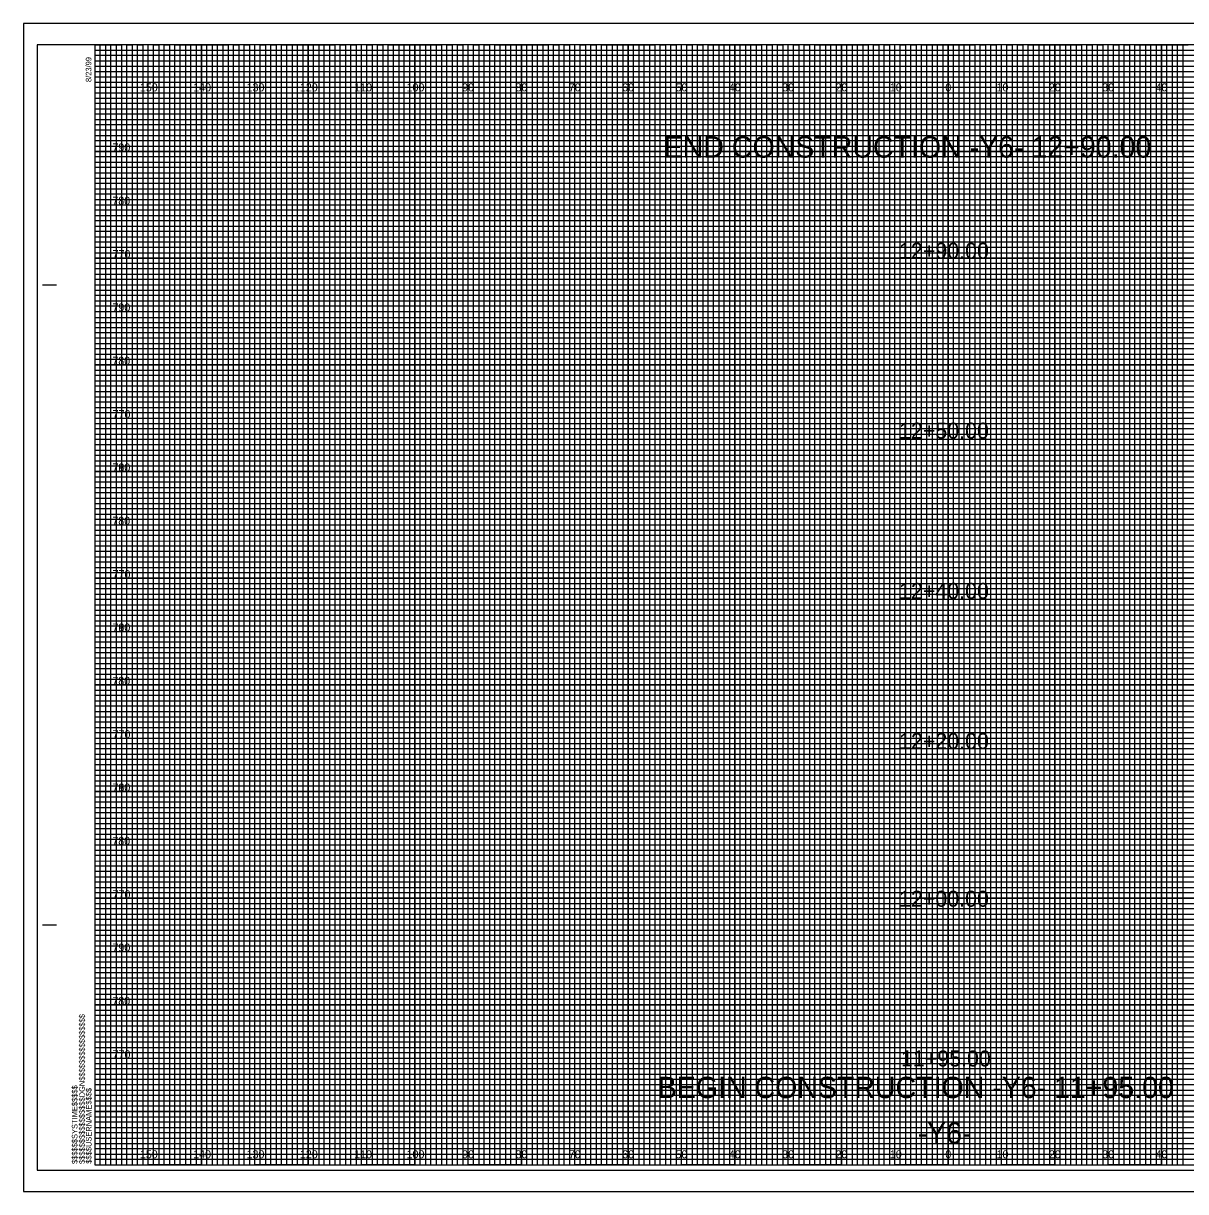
# Model space of a CAD drawing. Extents: x -13 to 323, y -5 to 214.
# Drawn here: x -13.4 to 204.5, y -5 to 214 of the extents above; entities that cross this region are included whole.
import ezdxf

# ---------------------------------------------------------------- set-up
doc = ezdxf.new("R2010")
doc.units = 0
for name, color, linetype in [('Prop XS Alignment Label', 7, 'Continuous'), ('Prop XS Elevation Labels', 7, 'Continuous'), ('Prop XS Offset Labels', 7, 'Continuous'), ('Prop XS Station Labels', 7, 'Continuous'), ('Sheet Cross Section CELL', 7, 'Continuous'), ('Sheet Cross Section Grid Major CELL', 7, 'Continuous'), ('Sheet Cross Section Grid Middle CELL', 7, 'Continuous'), ('Sheet Cross Section Grid Minor 1 CELL', 7, 'Continuous'), ('Sheet Cross Section Grid Minor 2 CELL', 7, 'Continuous'), ('Sheet Cutting Line CELL', 7, 'Continuous'), ('Sheet DOT Grid CELL', 7, 'Continuous'), ('Sheet Plot Border Inside CELL', 7, 'Continuous'), ('Sheet Plot Border Outside CELL', 7, 'Continuous')]:
    doc.layers.add(name, color=color, linetype=linetype)

msp = doc.modelspace()

# ---------------------------------------------------------------- linework, layer by layer
at = {"layer": 'Sheet Cross Section CELL'}
for p, q in [((-9.8, 165), (-7.3, 165)), ((-9.7, 165), (-7.2, 165)), ((-9.8, 45), (-7.3, 45)), ((-9.7, 45), (-7.2, 45)), ((0, 0), (0, 0)), ((0, 0), (0, 0)), ((0, 0), (0, 0)), ((0, 0), (0, 0)), ((0, 0), (0, 0)), ((0, 0), (0, 0)), ((0, 0), (0, 0))]:
    msp.add_line(p, q, dxfattribs=at)
msp.add_lwpolyline([(320, 210), (0, 210), (0, 0), (320, 0)], close=True, dxfattribs=at)
at = {"layer": 'Sheet Cross Section Grid Major CELL'}
for p, q in [((10, 210), (0, 210)), ((10, 0), (10, 210)), ((30, 210), (20, 210)), ((20, 210), (20, 0)), ((30, 0), (30, 210)), ((50, 210), (40, 210)), ((40, 210), (40, 0)), ((50, 0), (50, 210)), ((70, 210), (60, 210)), ((60, 210), (60, 0)), ((70, 0), (70, 210)), ((90, 210), (80, 210)), ((80, 210), (80, 0)), ((90, 0), (90, 210)), ((110, 210), (100, 210)), ((100, 210), (100, 0)), ((110, 0), (110, 210)), ((130, 210), (120, 210)), ((120, 210), (120, 0)), ((130, 0), (130, 210)), ((150, 210), (140, 210)), ((140, 210), (140, 0)), ((150, 0), (150, 210)), ((170, 210), (160, 210)), ((160, 210), (160, 0)), ((170, 0), (170, 210)), ((190, 210), (180, 210)), ((180, 210), (180, 0)), ((190, 0), (190, 210)), ((210, 210), (200, 210)), ((200, 210), (200, 0)), ((20, 0), (10, 0)), ((40, 0), (30, 0)), ((60, 0), (50, 0)), ((80, 0), (70, 0)), ((100, 0), (90, 0)), ((120, 0), (110, 0)), ((140, 0), (130, 0)), ((160, 0), (150, 0)), ((180, 0), (170, 0)), ((200, 0), (190, 0))]:
    msp.add_line(p, q, dxfattribs=at)
for points in [[(0, 200), (320, 200), (320, 190), (0, 190)], [(0, 180), (320, 180), (320, 170), (0, 170)], [(0, 160), (320, 160), (320, 150), (0, 150)], [(0, 140), (320, 140), (320, 130), (0, 130)], [(0, 120), (320, 120), (320, 110), (0, 110)], [(0, 100), (320, 100), (320, 90), (0, 90)], [(0, 80), (320, 80), (320, 70), (0, 70)], [(0, 60), (320, 60), (320, 50), (0, 50)], [(0, 40), (320, 40), (320, 30), (0, 30)], [(0, 20), (320, 20), (320, 10), (0, 10)]]:
    msp.add_lwpolyline(points, dxfattribs=at)
at = {"layer": 'Sheet Cross Section Grid Middle CELL'}
for points in [[(0, 210), (5, 210), (5, 0), (15, 0), (15, 210), (25, 210), (25, 0), (35, 0), (35, 210), (45, 210), (45, 0), (55, 0), (55, 210), (65, 210), (65, 0), (75, 0), (75, 210), (85, 210), (85, 0), (95, 0), (95, 210), (105, 210), (105, 0), (115, 0), (115, 210), (125, 210), (125, 0), (135, 0), (135, 210), (145, 210), (145, 0), (155, 0), (155, 210), (165, 210), (165, 0), (175, 0), (175, 210), (185, 210), (185, 0), (195, 0), (195, 210), (205, 210)], [(0, 205), (275, 205)], [(0, 185), (320, 185), (320, 195), (0, 195)], [(0, 165), (320, 165), (320, 175), (0, 175)], [(0, 145), (320, 145), (320, 155), (0, 155)], [(0, 125), (320, 125), (320, 135), (0, 135)], [(0, 105), (320, 105), (320, 115), (0, 115)], [(0, 85), (320, 85), (320, 95), (0, 95)], [(0, 65), (320, 65), (320, 75), (0, 75)], [(0, 45), (320, 45), (320, 55), (0, 55)], [(0, 25), (320, 25), (320, 35), (0, 35)], [(0, 5), (320, 5), (320, 15), (0, 15)]]:
    msp.add_lwpolyline(points, dxfattribs=at)
at = {"layer": 'Sheet Cross Section Grid Minor 1 CELL'}
for p, q in [((0, 209), (260, 209)), ((260, 207.98), (0, 207.98)), ((0, 207.98), (0, 207)), ((0, 207), (260, 207)), ((260, 205.89), (0, 205.89)), ((0, 205.89), (0, 204)), ((0, 204), (320, 204))]:
    msp.add_line(p, q, dxfattribs=at)
for points in [[(0, 203), (270, 203), (320, 203), (320, 202), (0, 202)], [(0, 201), (320, 201), (320, 199), (0, 199)], [(0, 198), (320, 198), (320, 197), (0, 196.98)], [(0, 196), (320, 196), (320, 194), (0, 194)], [(0, 193), (320, 193), (320, 192), (0, 192)], [(0, 191), (320, 191), (320, 189), (0, 189)], [(0, 188), (320, 188), (320, 187), (0, 187)], [(0, 186), (320, 186), (320, 184), (0, 184)], [(0, 183), (320, 183), (320, 182), (0, 182)], [(0, 181), (320, 181), (320, 179), (0, 179)], [(0, 178), (320, 178), (320, 177), (0, 177)], [(0, 176), (320, 176), (320, 173.95), (320, 173), (320, 172), (0, 172)], [(0, 174), (320, 174), (320, 173), (0, 173)], [(0, 171), (320, 171), (320, 169), (0, 169.03)], [(0, 169.03), (320, 169), (320, 168), (0, 168)], [(0, 167), (320, 167), (320, 166), (0, 166)], [(0, 164), (320, 164), (320, 163), (0, 163)], [(0, 162), (320, 162), (320, 161), (0, 161)], [(-0.07, 158.89), (320, 158.89), (320, 157.88), (-0.07, 157.88)], [(0, 157), (320, 157), (320, 156), (0, 156)], [(0, 154), (320, 154), (320, 153), (0, 153)], [(0, 152), (320, 152), (320, 151), (0, 151)], [(0, 149), (320, 149), (320, 148), (0, 148)], [(0, 147), (320, 147), (320, 146), (0, 146)], [(0, 144), (320, 144), (320, 143), (0, 143)], [(0, 142), (320, 142), (320, 141), (0, 141)], [(0, 139), (320, 139), (319.99, 137.98), (0, 138)], [(0, 137), (320, 137), (320, 136), (0, 136)], [(0, 134), (320, 134), (320, 133), (0, 133)], [(0, 132), (320, 132), (320, 131), (0, 131)], [(0, 129), (320, 129), (320, 128), (0, 128)], [(0, 127), (320, 127), (320, 126), (0, 126)], [(0, 124), (320, 124), (320, 123), (0, 123)], [(0, 122), (320, 122), (320, 121), (0, 121)], [(0, 119), (320, 119), (320, 118), (0, 118)], [(0, 116.99), (320.07, 116.91), (320, 116), (0, 116)], [(0, 114), (320, 114), (320, 113), (0, 113)], [(0, 112), (320, 112), (320, 111), (0, 111)], [(0, 109), (320, 109), (320, 108), (0, 108)], [(0, 107), (320, 107), (320, 106), (0, 106)], [(0, 104), (320, 104), (320, 103), (0, 103)], [(0, 102), (320, 102), (320, 101), (0, 101)], [(0, 99), (320, 99), (320, 98), (0, 98)], [(0, 97), (320, 97), (320, 96), (0, 96)], [(0, 94), (320, 94), (320, 93), (0, 93)], [(0, 92), (320, 92), (320, 91), (0, 91)], [(0, 89), (320, 89), (320, 88), (0, 88)], [(0, 87), (320, 87), (320, 86), (0, 86)], [(0, 84), (320, 84), (320, 83), (0, 83)], [(0, 82), (320, 82), (320, 81), (0, 81)], [(0, 79), (320, 79), (319.99, 77.98), (0, 78)], [(0, 77), (320, 77), (320, 76), (0, 76)], [(0, 74), (320, 74), (320, 73), (0, 73)], [(0, 72), (320, 72), (320, 71), (0, 71)], [(0, 69), (320, 69), (320, 68), (0, 68)], [(0, 67), (320, 67), (320, 66), (0, 66)], [(0, 64), (320, 64), (320, 63), (0, 63)], [(0, 62), (320, 62), (320, 61), (0, 61)], [(0, 59), (320, 59), (320, 58), (0, 58)], [(0, 56.99), (320.07, 56.91), (320, 56), (0, 56)], [(0, 54), (320, 54), (320, 53), (0, 53)], [(0, 52), (320, 52), (320, 51), (0, 51)], [(0, 49), (320, 49), (320, 48), (0, 48)], [(0, 47), (320, 47), (320, 46), (0, 46)], [(0, 44), (320, 44), (320, 43), (0, 43)], [(0, 42), (320, 42), (320, 41), (0, 41)], [(0, 39), (320, 39), (320, 38), (0, 38)], [(0, 37), (320, 37), (320, 36), (0, 36)], [(0, 34), (320, 34), (320, 33), (0, 33)], [(0, 32), (320, 32), (320, 31), (0, 31)], [(0, 29), (320, 29), (320, 28), (0, 28)], [(0, 27), (320, 27), (320, 26), (0, 26)], [(0, 24), (320, 24), (320, 23), (0, 23)], [(0, 22), (320, 22), (320, 21), (0, 21)], [(0, 19), (320, 19), (320, 18), (0, 18)], [(0, 17), (320, 17), (320, 16), (0, 16)], [(0, 14), (320, 14), (320, 13), (0, 13)], [(0, 12), (320, 12), (320, 11), (0, 11)], [(0, 9), (320, 9), (320, 8), (0, 8)], [(0, 7), (320, 7), (320, 6), (0, 6)], [(0, 4), (320, 4), (320, 3), (0, 3)], [(0, 2), (320, 2), (320, 1), (0, 1)]]:
    msp.add_lwpolyline(points, dxfattribs=at)
at = {"layer": 'Sheet Cross Section Grid Minor 2 CELL'}
for points in [[(0, 0), (1, 0), (1, 210), (2, 210), (2, 0)], [(2, 0), (3, 0), (3, 210), (4, 210), (4, 0)], [(5, 0), (6, 0), (6, 210), (7, 210), (7, 0)], [(7, 0), (8, 0), (8, 210), (9, 210), (9, 0)], [(10, 0), (11, 0), (11, 210), (12, 210), (12, 0)], [(12, 0), (13, 0), (13, 210), (14, 210), (14, 0)], [(15, 0), (16, 0), (16, 210), (17, 210), (17, 0)], [(17, 0), (18, 0), (18, 210), (19, 210), (19, 0)], [(20, 0), (21, 0), (21, 210), (22, 210), (22, 0)], [(22, 0), (23, 0), (23, 210), (24, 210), (24, 0)], [(25, 0), (26, 0), (26, 210), (27, 210), (27, 0)], [(27, 0), (28, 0), (28, 210), (29, 210), (29, 0)], [(30, 0), (31, 0), (31, 210), (32, 210), (32, 0)], [(32, 0), (33, 0), (33, 210), (34, 210), (34, 0)], [(35, 0), (36, 0), (36, 210), (37, 210), (37, 0)], [(37, 0), (38, 0), (38, 210), (39, 210), (39, 0)], [(40, 0), (41, 0), (41, 210), (42, 210), (42, 0)], [(42, 0), (43, 0), (43, 210), (44, 210), (44, 0)], [(45, 0), (46, 0), (46, 210), (47, 210), (47, 0)], [(47, 0), (48, 0), (48, 210), (49, 210), (49, 0)], [(50, 0), (51, 0), (51, 210), (52, 210), (52, 0)], [(52, 0), (53, 0), (53, 210), (54, 210), (54, 0)], [(55, 0), (56, 0), (56, 210), (57, 210), (57, 0)], [(57, 0), (58, 0), (58, 210), (59, 210), (59, 0)], [(60, 0), (61, 0), (61, 210), (62, 210), (62, 0)], [(62, 0), (63, 0), (63, 210), (64, 210), (64, 0)], [(65, 0), (66, 0), (66, 210), (67, 210), (67, 0)], [(67, 0), (68, 0), (68, 210), (69, 210), (69, 0)], [(70, 0), (71, 0), (71, 210), (72, 210), (72, 0)], [(72, 0), (73, 0), (73, 210), (74, 210), (74, 0)], [(75, 0), (76, 0), (76, 210), (77, 210), (77, 0)], [(77, 0), (78, 0), (78, 210), (79, 210), (79, 0)], [(80, 0), (81, 0), (81, 210), (82, 210), (82, 0)], [(82, 0), (83, 0), (83, 210), (84, 210), (84, 0)], [(85, 0), (86, 0), (86, 210), (87, 210), (87, 0)], [(87, 0), (88, 0), (88, 210), (89, 210), (89, 0)], [(90, 0), (91, 0), (91, 210), (92, 210), (92, 0)], [(92, 0), (93, 0), (93, 210), (94, 210), (94, 0)], [(95, 0), (96, 0), (96, 210), (97, 210), (97, 0)], [(97, 0), (98, 0), (98, 210), (99, 210), (99, 0)], [(100, 0), (101, 0), (101, 210), (102, 210), (102, 0)], [(102, 0), (103, 0), (103, 210), (104, 210), (104, 0)], [(105, 0), (106, 0), (106, 210), (107, 210), (107, 0)], [(107, 0), (108, 0), (108, 210), (109, 210), (109, 0)], [(110, 0), (111, 0), (111, 210), (112, 210), (112, 0)], [(112, 0), (113, 0), (113, 210), (114, 210), (114, 0)], [(115, 0), (116, 0), (116, 210), (117, 210), (117, 0)], [(117, 0), (118, 0), (118, 210), (119, 210), (119, 0)], [(120, 0), (121, 0), (121, 210), (122, 210), (122, 0)], [(122, 0), (123, 0), (123, 210), (124, 210), (124, 0)], [(125, 0), (126, 0), (126, 210), (127, 210), (127, 0)], [(127, 0), (128, 0), (128, 210), (129, 210), (129, 0)], [(130, 0), (131, 0), (131, 210), (132, 210), (132, 0)], [(132, 0), (133, 0), (133, 210), (134, 210), (134, 0)], [(135, 0), (136, 0), (136, 210), (137, 210), (137, 0)], [(137, 0), (138, 0), (138, 210), (139, 210), (139, 0)], [(140, 0), (141, 0), (141, 210), (142, 210), (142, 0)], [(142, 0), (143, 0), (143, 210), (144, 210), (144, 0)], [(145, 0), (146, 0), (146, 210), (147, 210), (147, 0)], [(147, 0), (148, 0), (148, 210), (149, 210), (149, 0)], [(150, 0), (151, 0), (151, 210), (152, 210), (152, 0)], [(152, 0), (153, 0), (153, 210), (154, 210), (154, 0)], [(155, 0), (156, 0), (156, 210), (157, 210), (157, 0)], [(157, 0), (158, 0), (158, 210), (159, 210), (159, 0)], [(160, 0), (161, 0), (161, 210), (162, 210), (162, 0)], [(162, 0), (163, 0), (163, 210), (164, 210), (164, 0)], [(165, 0), (166, 0), (166, 210), (167, 210), (167, 0)], [(167, 0), (168, 0), (168, 210), (169, 210), (169, 0)], [(170, 0), (171, 0), (171, 210), (172, 210), (172, 0)], [(172, 0), (173, 0), (173, 210), (174, 210), (174, 0)], [(175, 0), (176, 0), (176, 210), (177, 210), (177, 0)], [(177, 0), (178, 0), (178, 210), (179, 210), (179, 0)], [(180, 0), (181, 0), (181, 210), (182, 210), (182, 0)], [(182, 0), (183, 0), (183, 210), (184, 210), (184, 0)], [(185, 0), (186, 0), (186, 210), (187, 210), (187, 0)], [(187, 0), (188, 0), (188, 210), (189, 210), (189, 0)], [(190, 0), (191, 0), (191, 210), (192, 210), (192, 0)], [(192, 0), (193, 0), (193, 210), (194, 210), (194, 0)], [(195, 0), (196, 0), (196, 210), (197, 210), (197, 0)], [(197, 0), (198, 0), (198, 210), (199, 210), (199, 0)], [(200, 0), (201, 0), (201, 210), (202, 210), (202, 0)], [(202, 0), (203, 0), (203, 210), (204, 210), (204, 0)]]:
    msp.add_lwpolyline(points, dxfattribs=at)
at = {"layer": 'Sheet Cutting Line CELL'}
for p, q in [((323.3, 214), (-13.4, 214)), ((-13.4, 214), (-13.4, -5)), ((-13.4, -5), (323.3, -5))]:
    msp.add_line(p, q, dxfattribs=at)
at = {"layer": 'Sheet DOT Grid CELL'}
for p, q in [((10, 0), (10, 210)), ((20, 0), (20, 210)), ((30, 0), (30, 210)), ((40, 0), (40, 210)), ((50, 0), (50, 210)), ((60, 0), (60, 210)), ((70, 0), (70, 210)), ((80, 0), (80, 210)), ((90, 0), (90, 210)), ((100, 0), (100, 210)), ((110, 0), (110, 210)), ((120, 0), (120, 210)), ((130, 0), (130, 210)), ((140, 0), (140, 210)), ((150, 0), (150, 210)), ((160, 0), (160, 210)), ((170, 0), (170, 210)), ((180, 0), (180, 210)), ((190, 0), (190, 210)), ((200, 0), (200, 210)), ((0, 200), (320, 200)), ((0, 190), (320, 190)), ((0, 180), (320, 180)), ((0, 170), (320, 170)), ((0, 160), (320, 160)), ((0, 150), (320, 150)), ((0, 140), (320, 140)), ((0, 130), (320, 130)), ((0, 120), (320, 120)), ((0, 110), (320, 110)), ((0, 100), (320, 100)), ((0, 90), (320, 90)), ((0, 80), (320, 80)), ((0, 70), (320, 70)), ((0, 60), (320, 60)), ((0, 50), (320, 50)), ((0, 40), (320, 40)), ((0, 30), (320, 30)), ((0, 20), (320, 20)), ((0, 10), (320, 10))]:
    msp.add_line(p, q, dxfattribs=at)
at = {"layer": 'Sheet Plot Border Inside CELL'}
msp.add_lwpolyline([(-10.8, -1), (322.4, -1), (322.4, 210), (-10.8, 210)], close=True, dxfattribs=at)
at = {"layer": 'Sheet Plot Border Outside CELL'}
msp.add_lwpolyline([(-13.4, -5), (323.3, -5), (323.3, 214), (-13.4, 214)], close=True, dxfattribs=at)

# ---------------------------------------------------------------- texts
at = {"layer": 'Prop XS Alignment Label'}
for s, p in [('END CONSTRUCTION -Y6- 12+90.00', (106.65, 188.83)), ('BEGIN CONSTRUCTION -Y6- 11+95.00', (105.54, 12.53)), ('-Y6-', (154.25, 4))]:
    msp.add_text(s, height=4, dxfattribs=at).set_placement(p)
at = {"layer": 'Prop XS Elevation Labels'}
for s, p in [('790', (3.3, 190)), ('780', (3.28, 180)), ('770', (3.33, 170)), ('790', (3.3, 160)), ('780', (3.28, 150)), ('770', (3.33, 140)), ('790', (3.3, 130)), ('760', (3.3, 130)), ('780', (3.28, 120)), ('770', (3.33, 110)), ('790', (3.3, 100)), ('760', (3.3, 100)), ('780', (3.28, 90)), ('770', (3.33, 80)), ('790', (3.3, 70)), ('760', (3.3, 70)), ('780', (3.28, 60)), ('770', (3.33, 50)), ('790', (3.3, 40)), ('780', (3.28, 30)), ('770', (3.33, 20))]:
    msp.add_text(s, height=1.5, dxfattribs=at).set_placement(p)
at = {"layer": 'Prop XS Offset Labels'}
for s, p in [('150', (8.44, 201.25)), ('140', (18.44, 201.25)), ('130', (28.44, 201.25)), ('120', (38.44, 201.25)), ('110', (48.62, 201.25)), ('100', (58.44, 201.25)), ('90', (68.86, 201.25)), ('80', (78.86, 201.25)), ('70', (88.86, 201.25)), ('60', (98.86, 201.25)), ('50', (108.86, 201.25)), ('40', (118.86, 201.25)), ('30', (128.86, 201.25)), ('20', (138.86, 201.25)), ('10', (149.04, 201.25)), ('0', (159.45, 201.25)), ('0', (159.45, 201.25)), ('10', (169.04, 201.25)), ('20', (178.86, 201.25)), ('30', (188.86, 201.25)), ('40', (198.86, 201.25)), ('150', (8.44, 1.25)), ('140', (18.44, 1.25)), ('130', (28.44, 1.25)), ('120', (38.44, 1.25)), ('110', (48.62, 1.25)), ('100', (58.44, 1.25)), ('90', (68.86, 1.25)), ('80', (78.86, 1.25)), ('70', (88.86, 1.25)), ('60', (98.86, 1.25)), ('50', (108.86, 1.25)), ('40', (118.86, 1.25)), ('30', (128.86, 1.25)), ('20', (138.86, 1.25)), ('10', (149.04, 1.25)), ('0', (159.45, 1.25)), ('0', (159.45, 1.25)), ('10', (169.04, 1.25)), ('20', (178.86, 1.25)), ('30', (188.86, 1.25)), ('40', (198.86, 1.25))]:
    msp.add_text(s, height=1.5, dxfattribs=at).set_placement(p)
at = {"layer": 'Prop XS Station Labels'}
for s, p in [('12+90.00', (150.77, 169.87)), ('12+50.00', (150.77, 136.15)), ('12+40.00', (150.77, 106.11)), ('12+20.00', (150.77, 77.96)), ('12+00.00', (150.77, 48.41)), ('11+95.00', (151.13, 18.46))]:
    msp.add_text(s, height=3, dxfattribs=at).set_placement(p)
at = {"layer": 'Sheet Cross Section CELL'}
for s, p in [('8/23/99', (-0.65, 203)), ('$$$$$$$$$$$$$$$$DGN$$$$$$$$$$$$$$$$', (-1.88, 0.18)), ('$$$$$$SYSTIME$$$$$', (-3.26, 0.18)), ('$$$$USERNAME$$$$', (-0.62, 0.23))]:
    msp.add_text(s, height=1.05, rotation=90, dxfattribs=at).set_placement(p)

doc.saveas('drawing.dxf')
